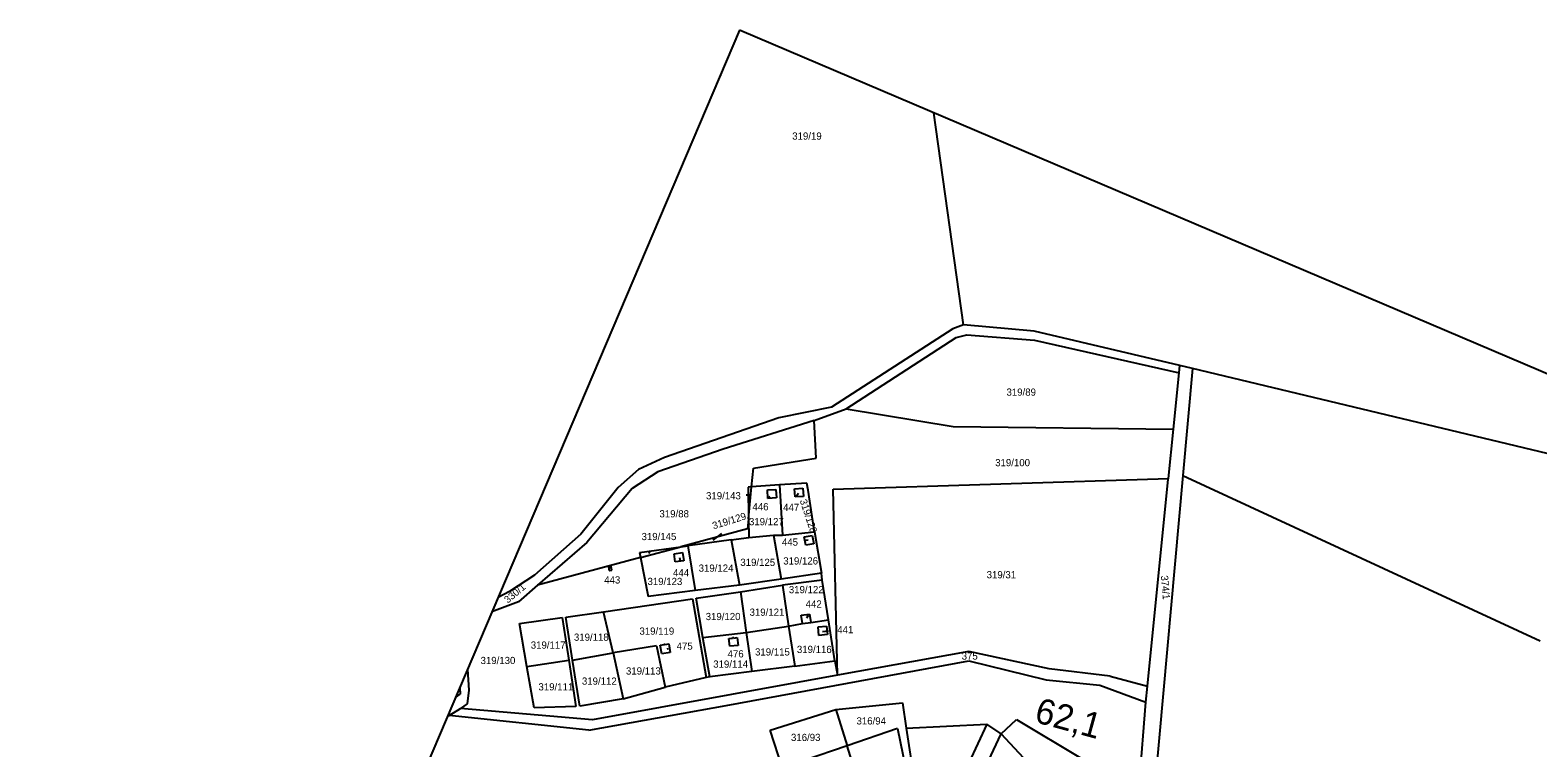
# Model space of a CAD drawing. Extents: x -805826 to -803822, y -1165880 to -1164382.
# Drawn here: x -805826 to -805114, y -1164721 to -1164382 of the extents above; entities that cross this region are included whole.
import ezdxf

# ---------------------------------------------------------------- set-up
doc = ezdxf.new("R2010")
doc.units = 0
for name, color, linetype in [('formát', 7, 'Continuous'), ('kilometráž - 2880', 7, 'Continuous'), ('kn_celek - Cisla parcel pomocna', 7, 'Continuous'), ('kn_celek - Cisla pozemkovych parcel', 7, 'Continuous'), ('kn_celek - Cisla stavebnich parcel', 7, 'Continuous'), ('kn_celek - Hranice parcel', 7, 'Continuous'), ('kn_celek - Vnitrni kresby', 7, 'Continuous')]:
    doc.layers.add(name, color=color, linetype=linetype)

msp = doc.modelspace()

# ---------------------------------------------------------------- linework, layer by layer
at = {"layer": 'formát'}
for p, q in [((-805491.17, -1164382.07), (-805826.05, -1165169.15)), ((-804934.65, -1164618.86), (-805491.17, -1164382.07))]:
    msp.add_line(p, q, dxfattribs=at)
at = {"layer": 'kn_celek - Cisla parcel pomocna'}
for p, q in [((-805486.46, -1164601.6), (-805488.06, -1164601.61)), ((-805476.86, -1164602.24), (-805477.44, -1164602.63)), ((-805463.26, -1164600.83), (-805464.41, -1164602.14)), ((-805503.61, -1164622.79), (-805499.5, -1164619.66)), ((-805458.78, -1164622.87), (-805460.57, -1164623.08)), ((-805533.76, -1164629.09), (-805533.33, -1164627.93)), ((-805519.44, -1164630.96), (-805519.22, -1164632.51)), ((-805459.34, -1164659.54), (-805458.51, -1164658.29)), ((-805451.92, -1164665.98), (-805449.05, -1164665.68)), ((-805525.29, -1164674.04), (-805524.66, -1164673.9))]:
    msp.add_line(p, q, dxfattribs=at)
at = {"layer": 'kn_celek - Hranice parcel'}
for p, q in [((-805500.15, -1164403.69), (-805500.37, -1164403.69)), ((-805500.17, -1164403.22), (-805500.15, -1164403.69)), ((-805385.32, -1164521.1), (-805399.34, -1164421.15)), ((-805390.49, -1164523.1), (-805447.69, -1164560.03)), ((-805385.32, -1164521.1), (-805390.49, -1164523.1)), ((-805351.96, -1164524.1), (-805385.32, -1164521.1)), ((-805283.29, -1164540.34), (-805351.96, -1164524.1)), ((-805440.83, -1164560.89), (-805388.82, -1164527.15)), ((-805388.82, -1164527.15), (-805383.8, -1164525.94)), ((-805383.8, -1164525.94), (-805351.89, -1164528.42)), ((-805351.89, -1164528.42), (-805283.63, -1164543.76)), ((-805286.31, -1164570.35), (-805283.63, -1164543.76)), ((-805283.63, -1164543.76), (-805283.29, -1164540.34)), ((-805277.24, -1164541.8), (-805283.29, -1164540.34)), ((-805277.24, -1164541.8), (-805281.83, -1164592.37)), ((-805083.45, -1164588.22), (-805277.24, -1164541.8)), ((-805447.69, -1164560.03), (-805472.6, -1164565.1)), ((-805455.83, -1164566.34), (-805440.83, -1164560.89)), ((-805440.83, -1164560.89), (-805390.2, -1164569.1)), ((-805472.6, -1164565.1), (-805526.56, -1164583.81)), ((-805455.83, -1164566.34), (-805498.87, -1164579.79)), ((-805454.97, -1164584.17), (-805455.83, -1164566.34)), ((-805390.2, -1164569.1), (-805286.31, -1164570.35)), ((-805288.52, -1164593.71), (-805286.31, -1164570.35)), ((-805498.87, -1164579.79), (-805529.69, -1164590.58)), ((-805538.76, -1164589.48), (-805548.49, -1164597.98)), ((-805526.56, -1164583.81), (-805538.76, -1164589.48)), ((-805485.4, -1164597.68), (-805484.55, -1164588.78)), ((-805484.55, -1164588.78), (-805454.97, -1164584.17)), ((-805529.69, -1164590.58), (-805541.88, -1164598.43)), ((-805472.22, -1164596.73), (-805485.4, -1164597.68)), ((-805459.3, -1164595.86), (-805472.22, -1164596.73)), ((-805472.22, -1164596.73), (-805470.84, -1164620.4)), ((-805458.79, -1164599.18), (-805459.3, -1164595.86)), ((-805446.9, -1164598.82), (-805288.52, -1164593.71)), ((-805298.55, -1164691.68), (-805288.7, -1164594.09)), ((-805281.83, -1164592.37), (-805297.72, -1164767.78)), ((-805288.7, -1164594.09), (-805288.52, -1164593.71)), ((-805281.83, -1164592.37), (-805113.11, -1164670.31)), ((-805548.49, -1164597.98), (-805565.99, -1164619.94)), ((-805541.88, -1164598.43), (-805563.2, -1164623.97)), ((-805485.4, -1164597.68), (-805487.07, -1164597.81)), ((-805487.07, -1164597.81), (-805486.84, -1164612.7)), ((-805486.84, -1164612.7), (-805485.4, -1164597.68)), ((-805477.99, -1164599.11), (-805473.97, -1164598.88)), ((-805477.75, -1164603.1), (-805477.99, -1164599.11)), ((-805473.71, -1164602.86), (-805477.75, -1164603.1)), ((-805473.97, -1164598.88), (-805473.71, -1164602.86)), ((-805465.2, -1164598.55), (-805461.25, -1164598.25)), ((-805464.92, -1164602.44), (-805465.2, -1164598.55)), ((-805460.95, -1164602.18), (-805464.92, -1164602.44)), ((-805461.25, -1164598.25), (-805460.95, -1164602.18)), ((-805455.7, -1164618.91), (-805458.79, -1164599.18)), ((-805444.91, -1164686.48), (-805446.9, -1164598.82)), ((-805487.3, -1164617.46), (-805518.82, -1164625.94)), ((-805486.84, -1164612.7), (-805487.3, -1164617.46)), ((-805486.84, -1164612.7), (-805486.72, -1164621.59)), ((-805565.99, -1164619.94), (-805587.86, -1164639.35)), ((-805563.2, -1164623.97), (-805586.51, -1164644.03)), ((-805495, -1164622.69), (-805515.56, -1164625.47)), ((-805495, -1164622.69), (-805486.72, -1164621.59)), ((-805495, -1164622.69), (-805491.14, -1164644.1)), ((-805486.72, -1164621.59), (-805475.09, -1164620.54)), ((-805475.09, -1164620.54), (-805470.84, -1164620.4)), ((-805475.09, -1164620.54), (-805471.46, -1164641.27)), ((-805470.84, -1164620.4), (-805455.7, -1164618.91)), ((-805460.63, -1164621.32), (-805456.79, -1164620.63)), ((-805459.86, -1164625.23), (-805460.63, -1164621.32)), ((-805456.03, -1164624.5), (-805459.86, -1164625.23)), ((-805456.79, -1164620.63), (-805456.03, -1164624.5)), ((-805455.7, -1164618.91), (-805452.45, -1164638.35)), ((-805537.84, -1164631.04), (-805586.51, -1164644.03)), ((-805538.31, -1164628.7), (-805518.82, -1164625.94)), ((-805538.31, -1164628.7), (-805537.84, -1164631.04)), ((-805537.84, -1164631.04), (-805518.82, -1164625.94)), ((-805537.84, -1164631.04), (-805534.21, -1164649.36)), ((-805522.03, -1164629.24), (-805518.06, -1164628.63)), ((-805521.5, -1164633.1), (-805522.03, -1164629.24)), ((-805518.82, -1164625.94), (-805515.56, -1164625.47)), ((-805518.06, -1164628.63), (-805517.47, -1164632.52)), ((-805515.56, -1164625.47), (-805512.15, -1164646.58)), ((-805587.86, -1164639.35), (-805599.68, -1164647.11)), ((-805551.74, -1164635.12), (-805552.94, -1164635.35)), ((-805552.94, -1164635.35), (-805552.6, -1164637.12)), ((-805552.6, -1164637.12), (-805552.47, -1164637.11)), ((-805552.47, -1164637.11), (-805551.52, -1164636.94)), ((-805551.42, -1164636.92), (-805551.74, -1164635.12)), ((-805551.52, -1164636.94), (-805551.42, -1164636.92)), ((-805517.47, -1164632.52), (-805521.5, -1164633.1)), ((-805452.45, -1164638.35), (-805471.46, -1164641.27)), ((-805452.1, -1164641.63), (-805452.45, -1164638.35)), ((-805586.51, -1164644.03), (-805595.46, -1164651.91)), ((-805512.15, -1164646.58), (-805534.21, -1164649.36)), ((-805491.14, -1164644.1), (-805512.15, -1164646.58)), ((-805471.46, -1164641.27), (-805491.14, -1164644.1)), ((-805490.68, -1164647.15), (-805470.89, -1164644.1)), ((-805452.1, -1164641.63), (-805470.89, -1164644.1)), ((-805470.89, -1164644.1), (-805468.08, -1164663.39)), ((-805449.05, -1164660.42), (-805452.1, -1164641.63)), ((-805595.46, -1164651.91), (-805608.03, -1164656.73)), ((-805599.68, -1164647.11), (-805605.15, -1164649.95)), ((-805555.33, -1164656.59), (-805513.41, -1164650.54)), ((-805513.41, -1164650.54), (-805506.89, -1164687.64)), ((-805511.61, -1164650.19), (-805490.68, -1164647.15)), ((-805508.48, -1164668.8), (-805511.61, -1164650.19)), ((-805490.68, -1164647.15), (-805487.98, -1164666.44)), ((-805595, -1164662.23), (-805574.83, -1164659.25)), ((-805574.83, -1164659.25), (-805571.7, -1164679.49)), ((-805573.16, -1164659.1), (-805555.33, -1164656.59)), ((-805570.05, -1164679.5), (-805573.16, -1164659.1)), ((-805550.84, -1164676.06), (-805555.33, -1164656.59)), ((-805461.98, -1164658.24), (-805458.05, -1164657.69)), ((-805461.41, -1164662.2), (-805461.98, -1164658.24)), ((-805458.05, -1164657.69), (-805457.52, -1164661.66)), ((-805457.52, -1164661.66), (-805449.05, -1164660.42)), ((-805446.14, -1164679.77), (-805449.05, -1164660.42)), ((-805591.51, -1164682.42), (-805595, -1164662.23)), ((-805508.48, -1164668.8), (-805487.98, -1164666.44)), ((-805487.98, -1164666.44), (-805468.08, -1164663.39)), ((-805487.98, -1164666.44), (-805485.27, -1164684.83)), ((-805468.08, -1164663.39), (-805461.41, -1164662.2)), ((-805468.08, -1164663.39), (-805464.99, -1164682.28)), ((-805461.41, -1164662.2), (-805457.52, -1164661.66)), ((-805453.99, -1164663.79), (-805450.05, -1164663.42)), ((-805453.61, -1164667.79), (-805453.99, -1164663.79)), ((-805449.65, -1164667.4), (-805453.61, -1164667.79)), ((-805450.05, -1164663.42), (-805449.65, -1164667.4)), ((-805530.32, -1164672.75), (-805550.84, -1164676.06)), ((-805530.32, -1164672.75), (-805526.3, -1164692.26)), ((-805528.62, -1164672.42), (-805526.78, -1164672.1)), ((-805527.87, -1164676.55), (-805528.62, -1164672.42)), ((-805526.8, -1164671.96), (-805526.4, -1164671.89)), ((-805526.78, -1164672.1), (-805526.8, -1164671.96)), ((-805526.4, -1164671.89), (-805526.38, -1164672.03)), ((-805526.38, -1164672.03), (-805524.58, -1164671.71)), ((-805524.58, -1164671.71), (-805523.85, -1164675.82)), ((-805505.19, -1164687.29), (-805508.48, -1164668.8)), ((-805496.14, -1164669.29), (-805494.41, -1164669.07)), ((-805495.73, -1164672.91), (-805496.14, -1164669.29)), ((-805491.79, -1164672.49), (-805495.73, -1164672.91)), ((-805494.45, -1164668.78), (-805493.85, -1164668.7)), ((-805494.41, -1164669.07), (-805494.45, -1164668.78)), ((-805493.85, -1164668.7), (-805493.81, -1164669.01)), ((-805493.81, -1164669.01), (-805492.22, -1164668.82)), ((-805492.22, -1164668.82), (-805491.79, -1164672.49)), ((-805591.51, -1164682.42), (-805571.7, -1164679.49)), ((-805571.7, -1164679.49), (-805568.36, -1164701.28)), ((-805570.05, -1164679.5), (-805550.84, -1164676.06)), ((-805566.58, -1164701.19), (-805570.05, -1164679.5)), ((-805550.84, -1164676.06), (-805546.02, -1164697.77)), ((-805523.85, -1164675.82), (-805527.87, -1164676.55)), ((-805497.42, -1164700.86), (-805382.87, -1164679.86)), ((-805464.99, -1164682.28), (-805485.27, -1164684.83)), ((-805464.99, -1164682.28), (-805446.14, -1164679.77)), ((-805446.14, -1164679.77), (-805444.91, -1164686.48)), ((-805382.91, -1164675.4), (-805444.91, -1164686.48)), ((-805344.9, -1164683.54), (-805382.91, -1164675.4)), ((-805382.87, -1164679.86), (-805346.34, -1164688.8)), ((-805619.56, -1164683.82), (-805618.95, -1164693.56)), ((-805588.1, -1164702), (-805591.51, -1164682.42)), ((-805506.89, -1164687.64), (-805526.3, -1164692.26)), ((-805485.27, -1164684.83), (-805505.19, -1164687.29)), ((-805444.91, -1164686.48), (-805462.97, -1164689.88)), ((-805346.34, -1164688.8), (-805320.98, -1164691.24)), ((-805316.06, -1164687.06), (-805344.9, -1164683.54)), ((-805316.06, -1164687.06), (-805298.55, -1164691.68)), ((-805625.18, -1164697.05), (-805623.03, -1164695.45)), ((-805623.23, -1164692.46), (-805623.03, -1164695.45)), ((-805618.95, -1164693.56), (-805619.77, -1164700.01)), ((-805462.97, -1164689.88), (-805560.57, -1164707.68)), ((-805546.02, -1164697.77), (-805526.3, -1164692.26)), ((-805320.98, -1164691.24), (-805299.25, -1164699.31)), ((-805299.25, -1164699.31), (-805298.55, -1164691.68)), ((-805628.21, -1164705.54), (-805622.83, -1164702.25)), ((-805619.77, -1164700.01), (-805622.83, -1164702.25)), ((-805560.57, -1164707.68), (-805622.83, -1164702.25)), ((-805568.36, -1164701.28), (-805588.1, -1164702)), ((-805546.02, -1164697.77), (-805566.58, -1164701.19)), ((-805562.32, -1164712.59), (-805497.42, -1164700.86)), ((-805476.69, -1164712.54), (-805445.72, -1164702.79)), ((-805445.72, -1164702.79), (-805414.22, -1164699.59)), ((-805445.72, -1164702.79), (-805440.33, -1164719.92)), ((-805414.22, -1164699.59), (-805412.4, -1164711.49)), ((-805305.32, -1164773.18), (-805299.25, -1164699.31)), ((-805628.83, -1164705.6), (-805628.21, -1164705.54)), ((-805562.32, -1164712.59), (-805628.21, -1164705.54)), ((-805412.4, -1164711.49), (-805374.33, -1164709.68)), ((-805374.33, -1164709.68), (-805389.77, -1164742.48)), ((-805367.6, -1164714.25), (-805374.33, -1164709.68)), ((-805367.6, -1164714.25), (-805360.34, -1164707.4)), ((-805360.34, -1164707.4), (-805329.31, -1164726.02)), ((-805470.84, -1164730.39), (-805476.69, -1164712.54)), ((-805416.61, -1164711.68), (-805440.33, -1164719.92)), ((-805416.61, -1164711.68), (-805408.85, -1164748.58)), ((-805412.4, -1164711.49), (-805406.69, -1164748.5)), ((-805383.12, -1164747), (-805367.6, -1164714.25)), ((-805343.79, -1164739.78), (-805367.6, -1164714.25)), ((-805440.33, -1164719.92), (-805460.68, -1164726.9)), ((-805430.19, -1164752.06), (-805440.33, -1164719.92))]:
    msp.add_line(p, q, dxfattribs=at)
at = {"layer": 'kn_celek - Vnitrni kresby'}
for p, q in [((-805552.68, -1164635.89), (-805551.72, -1164635.71)), ((-805552.47, -1164637.11), (-805552.68, -1164635.89)), ((-805551.72, -1164635.71), (-805551.52, -1164636.94)), ((-805505.19, -1164687.29), (-805506.89, -1164687.64))]:
    msp.add_line(p, q, dxfattribs=at)

# ---------------------------------------------------------------- texts
at = {"layer": 'kilometráž - 2880'}
msp.add_text('62,1', height=12, rotation=344.71257, dxfattribs=at).set_placement((-805352.42, -1164708.51))
at = {"layer": 'kn_celek - Cisla parcel pomocna'}
for s, p in [('319/143', (-805506.94, -1164603.55)), ('446', (-805485.01, -1164608.74)), ('447', (-805470.53, -1164609.04)), ('319/145', (-805537.39, -1164622.8)), ('445', (-805471.11, -1164625.41)), ('444', (-805522.53, -1164639.89)), ('443', (-805555.02, -1164643.28)), ('442', (-805459.91, -1164654.67)), ('441', (-805444.96, -1164666.77)), ('475', (-805520.82, -1164674.53)), ('476', (-805496.76, -1164678.19))]:
    msp.add_text(s, height=3.4, dxfattribs=at).set_placement(p)
msp.add_text('319/129', height=3.4, rotation=17.19, dxfattribs=at).set_placement((-805503.37, -1164617.73))
at = {"layer": 'kn_celek - Cisla pozemkovych parcel'}
for s, height, p in [('319/19', 3.4, (-805466.24, -1164433.76)), ('319/89', 3.4, (-805365.08, -1164554.63)), ('319/100', 3.4, (-805370.42, -1164587.92)), ('319/143', 0.005, (-805486.46, -1164601.6)), ('319/88', 3.4, (-805528.93, -1164612.07)), ('319/127', 3.4, (-805486.67, -1164615.77)), ('319/129', 0.005, (-805503.61, -1164622.79)), ('319/145', 0.005, (-805533.76, -1164629.09)), ('319/125', 3.4, (-805490.74, -1164634.99)), ('319/126', 3.4, (-805470.49, -1164634.31)), ('319/124', 3.4, (-805510.43, -1164637.71)), ('319/31', 3.4, (-805374.45, -1164640.83)), ('319/123', 3.4, (-805534.58, -1164644)), ('319/122', 3.4, (-805467.84, -1164647.86)), ('319/120', 3.4, (-805507.11, -1164660.56)), ('319/121', 3.4, (-805486.39, -1164658.51)), ('319/118', 3.4, (-805569.32, -1164670.31)), ('319/119', 3.4, (-805538.38, -1164667.45)), ('319/117', 3.4, (-805589.69, -1164674.04)), ('319/115', 3.4, (-805483.81, -1164677.27)), ('319/116', 3.4, (-805464.04, -1164676.08)), ('319/130', 3.4, (-805613.4, -1164681.31)), ('319/114', 3.4, (-805503.54, -1164683.02)), ('375', 3.4, (-805386.24, -1164679.22)), ('319/112', 3.4, (-805565.55, -1164691.05)), ('319/113', 3.4, (-805544.74, -1164686.25)), ('319/111', 3.4, (-805586.05, -1164693.75)), ('316/94', 3.4, (-805435.89, -1164709.83)), ('316/93', 3.4, (-805466.83, -1164717.62))]:
    msp.add_text(s, height=height, dxfattribs=at).set_placement(p)
for s, rotation, p in [('319/128', 288.369, (-805462.75, -1164604.14)), ('374/1', 274.905, (-805292.21, -1164639.59)), ('330/1', 40.05, (-805600.52, -1164652.82))]:
    msp.add_text(s, height=3.4, rotation=rotation, dxfattribs=at).set_placement(p)
at = {"layer": 'kn_celek - Cisla stavebnich parcel'}
for s, p in [('446', (-805476.86, -1164602.24)), ('447', (-805463.26, -1164600.83)), ('445', (-805458.78, -1164622.87)), ('444', (-805519.44, -1164630.96)), ('443', (-805552.11, -1164636.63)), ('442', (-805459.34, -1164659.54)), ('441', (-805451.92, -1164665.98)), ('475', (-805525.29, -1164674.04)), ('476', (-805493.85, -1164671.43))]:
    msp.add_text(s, height=0.005, dxfattribs=at).set_placement(p)

doc.saveas('drawing.dxf')
